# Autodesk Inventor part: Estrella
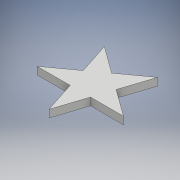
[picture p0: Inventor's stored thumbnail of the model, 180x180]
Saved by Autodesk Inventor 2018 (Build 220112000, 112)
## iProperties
Created: 2020-11
Part Number: Estrella
Material: Genérico
Document SubType Name: Modeling
Designer: ULISES
Density: 1 g/cm^3
Appearance: Valor por defecto
Author: ULISES
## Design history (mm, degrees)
sketch "Boceto1"
  geometry: L1 (0, 0)-(36.5, 0); L2 (36.5, 0)-(36.5, 35); L3 (36.5, 35)-(0, 35); L4 (0, 35)-(0, 0); L5 (18.25, 0.286)-(0, 13.546); L6 (0, 13.546)-(6.971, 35); L7 (6.971, 35)-(29.529, 35); L8 (29.529, 35)-(36.5, 13.546); L9 (36.5, 13.546)-(18.25, 0.286); L10 (0, 13.546)-(11.279, 21.741); L11 (18.25, 26.805)-(29.529, 35); L12 (6.971, 35)-(18.25, 26.805); L13 (25.221, 21.741)-(36.5, 13.546); L14 (18.25, 0.286)-(22.558, 13.546); L15 (25.221, 21.741)-(29.529, 35); L16 (0, 13.546)-(13.942, 13.546); L17 (22.558, 13.546)-(36.5, 13.546); L18 (6.971, 35)-(11.279, 21.741); L19 (13.942, 13.546)-(18.25, 0.286); 1 further point
  constraints: 38 end point, 3 horizontal, 2 parallel, 2 point on line, 1 collinear, 1 perpendicular, 11 other
  dimensions: "d0" = 35 distance of L3.end L1.start; "d1" = 36.5 distance of L1.start L1.end
extrude "Extrusión1" new body sketch "Boceto1" distance "d2" = 3.2; taper "d3" = 0 deg
node "Sólido1"
